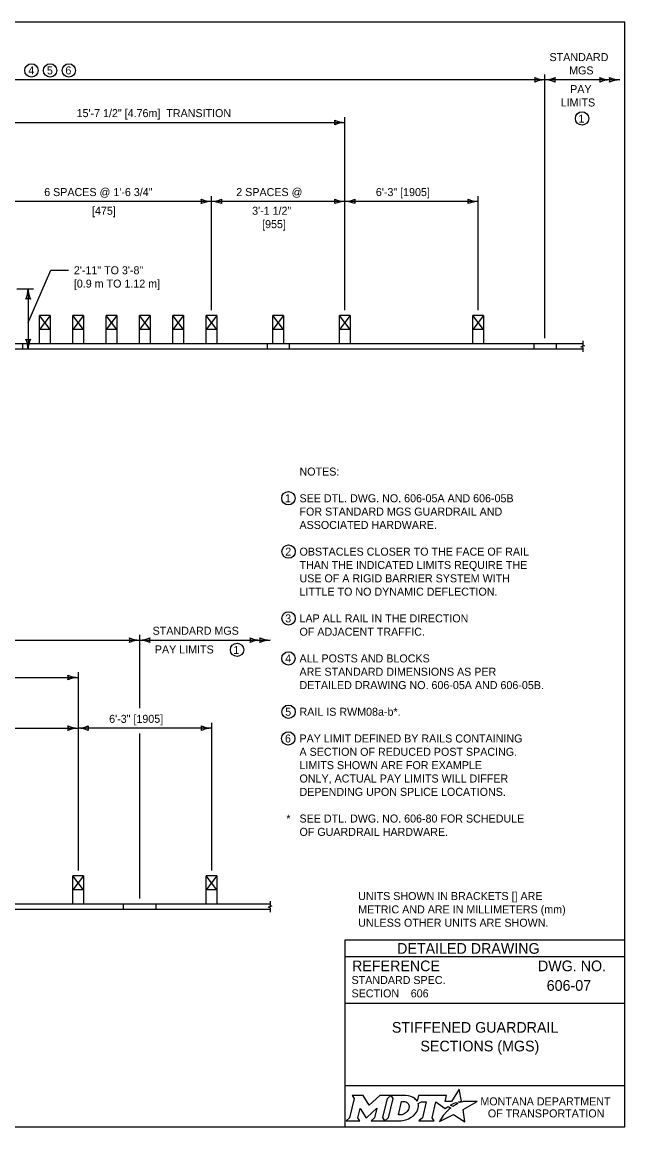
# Model space of a CAD drawing. Extents: x 49991.4 to 50044.5, y 49987.6 to 50011.4.
# Drawn here: x 50016.42 to 50020.94, y 49999.89 to 50008.16 of the extents above; entities that cross this region are included whole.
import ezdxf

# ---------------------------------------------------------------- set-up
doc = ezdxf.new("R2010")
doc.units = 0
for name, color, linetype in [('Default', 7, 'Continuous'), ('Level 1', 7, 'Continuous'), ('Level 2', 7, 'Continuous'), ('Level 3', 7, 'Continuous'), ('Level 4', 7, 'Continuous'), ('Level 6', 7, 'Continuous')]:
    doc.layers.add(name, color=color, linetype=linetype)

msp = doc.modelspace()

# ---------------------------------------------------------------- linework, layer by layer
at = {"layer": 'Default'}
for points in [[(50018.8933, 50000.1206), (50018.9074, 50000.0972), (50018.8739, 49999.9539), (50018.8482, 49999.9314), (50018.9498, 49999.9314), (50018.9363, 49999.9542), (50018.9525, 50000.0243), (50018.9962, 49999.9553), (50019.0015, 49999.9553), (50019.0766, 50000.0248), (50019.0602, 49999.9537), (50019.0355, 49999.9317), (50019.1371, 49999.9317), (50019.1233, 49999.955), (50019.1565, 50000.0974)], [(50019.1565, 50000.0974), (50019.1818, 50000.1206), (50019.0994, 50000.1206), (50019.0198, 50000.0476), (50018.9753, 50000.1203), (50018.8933, 50000.1206)], [(50019.2954, 50000.1206), (50019.1818, 50000.1206), (50019.1965, 50000.0977), (50019.1626, 49999.9539), (50019.1371, 49999.9317), (50019.2477, 49999.9317)], [(50019.7003, 50000.0679), (50019.69, 50000.0735), (50019.7016, 50000.0763), (50019.7132, 50000.0783), (50019.6958, 50000.1684), (50019.6363, 50000.0771), (50019.589, 50000.0764), (50019.5993, 50000.1205), (50019.3901, 50000.1206), (50019.38, 50000.0781), (50019.3742, 50000.0864)], [(50019.3194, 50000.0339), (50019.3182, 50000.0258), (50019.315, 50000.0165), (50019.3108, 50000.0083), (50019.3052, 50000.0008), (50019.2987, 49999.9939), (50019.2908, 49999.9876), (50019.2825, 49999.9829), (50019.2734, 49999.979), (50019.2643, 49999.9767), (50019.2551, 49999.9758), (50019.2392, 49999.9758), (50019.2628, 50000.0758), (50019.2788, 50000.0758), (50019.2864, 50000.0752), (50019.294, 50000.0733), (50019.3006, 50000.0703), (50019.3067, 50000.0661), (50019.3115, 50000.0611), (50019.3152, 50000.0551), (50019.3179, 50000.0489), (50019.3195, 50000.0415), (50019.3195, 50000.0385), (50019.3194, 50000.0339)], [(50019.3868, 50000.0615), (50019.4114, 50000.0746), (50019.4483, 50000.0746), (50019.4197, 49999.9541), (50019.3922, 49999.9314), (50019.5084, 49999.9314), (50019.4914, 49999.9543), (50019.5196, 50000.0745), (50019.5909, 50000.0228), (50019.612, 50000.0379), (50019.6317, 50000.027)], [(50019.5759, 49999.9711), (50019.5606, 49999.9467), (50019.5559, 49999.9392), (50019.5501, 49999.9306), (50019.5478, 49999.9263), (50019.6531, 49999.9794), (50019.737, 49999.9243), (50019.7239, 50000.017), (50019.8308, 50000.0754), (50019.7815, 50000.0762), (50019.7514, 50000.0766), (50019.7306, 50000.0769), (50019.7238, 50000.0754), (50019.7189, 50000.0742), (50019.7105, 50000.0719), (50019.7003, 50000.0679)], [(50019.6499, 50000.0403), (50019.6475, 50000.0386), (50019.6292, 50000.0482), (50019.6395, 50000.0539), (50019.6436, 50000.0561), (50019.6522, 50000.0601), (50019.6579, 50000.0627), (50019.6658, 50000.0657), (50019.6731, 50000.0684), (50019.6849, 50000.061), (50019.6809, 50000.0589), (50019.6763, 50000.0564), (50019.6721, 50000.0542), (50019.6671, 50000.0513), (50019.6652, 50000.0502), (50019.6625, 50000.0486), (50019.66, 50000.0472), (50019.6577, 50000.0456), (50019.6551, 50000.0438), (50019.6524, 50000.042), (50019.6499, 50000.0403)], [(50019.2934, 49999.939), (50019.3018, 49999.9416), (50019.3148, 49999.947), (50019.3352, 49999.958)], [(50019.5898, 49999.9872), (50019.5898, 49999.9872)]]:
    msp.add_lwpolyline(points, dxfattribs=at)
for centre, radius, start, end in [((50019.3185, 50000.0422), 0.0709, 339.53292, 15.85821), ((50019.2745, 50000.0595), 0.1183, 300.91025, 339.13831)]:
    msp.add_arc(centre, radius, start, end, dxfattribs=at)
for centre, major_axis, ratio, start_param, end_param in [((50019.2933, 50000.0732), (0.0834, -0.0037), 0.568097, 0.61298, 1.570796), ((50019.3489, 50000.0805), (0.0361, -0.0295), 0.469099, 1.225588, 1.570796), ((50019.6206, 50000.0173), (-0.0112, -0.0097), 0.021651, 3.157348, 6.283185), ((50019.5829, 49999.9791), (-0.00694, -0.00806), 0.008222, 0, 3.137361), ((50019.5996, 49999.9974), (-0.0098, -0.0102), 0.016458, 3.141593, 6.279097), ((50019.248, 50000.08), (0, 0.1484), 0.987302, 3.139398, 3.456847)]:
    msp.add_ellipse(centre, major_axis=major_axis, ratio=ratio, start_param=start_param, end_param=end_param, dxfattribs=at)
at = {"layer": 'Level 1'}
for p, q in [((50016.5483, 50005.7568), (50016.5483, 50005.9668)), ((50016.6271, 50005.8618), (50016.5483, 50005.9668)), ((50016.6271, 50005.9668), (50016.5483, 50005.8618)), ((50016.6271, 50005.9668), (50016.5483, 50005.9668)), ((50016.6271, 50005.9668), (50016.6271, 50005.7568)), ((50016.7983, 50005.7568), (50016.7983, 50005.9668)), ((50016.8771, 50005.8618), (50016.7983, 50005.9668)), ((50016.8771, 50005.9668), (50016.7983, 50005.8618)), ((50016.8771, 50005.9668), (50016.7983, 50005.9668)), ((50016.8771, 50005.9668), (50016.8771, 50005.7568)), ((50017.0483, 50005.7568), (50017.0483, 50005.9668)), ((50017.1271, 50005.8618), (50017.0483, 50005.9668)), ((50017.1271, 50005.9668), (50017.0483, 50005.8618)), ((50017.1271, 50005.9668), (50017.0483, 50005.9668)), ((50017.1271, 50005.9668), (50017.1271, 50005.7568)), ((50017.2983, 50005.7568), (50017.2983, 50005.9668)), ((50017.3771, 50005.8618), (50017.2983, 50005.9668)), ((50017.3771, 50005.9668), (50017.2983, 50005.8618)), ((50017.3771, 50005.9668), (50017.2983, 50005.9668)), ((50017.3771, 50005.9668), (50017.3771, 50005.7568)), ((50017.5483, 50005.7568), (50017.5483, 50005.9668)), ((50017.6271, 50005.8618), (50017.5483, 50005.9668)), ((50017.6271, 50005.9668), (50017.5483, 50005.8618)), ((50017.6271, 50005.9668), (50017.5483, 50005.9668)), ((50017.6271, 50005.9668), (50017.6271, 50005.7568)), ((50017.7983, 50005.7568), (50017.7983, 50005.9668)), ((50017.8771, 50005.8618), (50017.7983, 50005.9668)), ((50017.8771, 50005.9668), (50017.7983, 50005.8618)), ((50017.8771, 50005.9668), (50017.7983, 50005.9668)), ((50017.8771, 50005.9668), (50017.8771, 50005.7568)), ((50018.2983, 50005.7568), (50018.2983, 50005.9668)), ((50018.3771, 50005.8618), (50018.2983, 50005.9668)), ((50018.3771, 50005.9668), (50018.2983, 50005.8618)), ((50018.3771, 50005.9668), (50018.2983, 50005.9668)), ((50018.3771, 50005.9668), (50018.3771, 50005.7568)), ((50018.7983, 50005.7568), (50018.7983, 50005.9668)), ((50018.8771, 50005.8618), (50018.7983, 50005.9668)), ((50018.8771, 50005.9668), (50018.7983, 50005.8618)), ((50018.8771, 50005.9668), (50018.7983, 50005.9668)), ((50018.8771, 50005.9668), (50018.8771, 50005.7568)), ((50019.7983, 50005.7568), (50019.7983, 50005.9668)), ((50019.8771, 50005.8618), (50019.7983, 50005.9668)), ((50019.8771, 50005.9668), (50019.7983, 50005.8618)), ((50019.8771, 50005.9668), (50019.7983, 50005.9668)), ((50019.8771, 50005.9668), (50019.8771, 50005.7568)), ((50016.6271, 50005.8618), (50016.5483, 50005.8618)), ((50016.8771, 50005.8618), (50016.7983, 50005.8618)), ((50017.1271, 50005.8618), (50017.0483, 50005.8618)), ((50017.3771, 50005.8618), (50017.2983, 50005.8618)), ((50017.6271, 50005.8618), (50017.5483, 50005.8618)), ((50017.8771, 50005.8618), (50017.7983, 50005.8618)), ((50018.3771, 50005.8618), (50018.2983, 50005.8618)), ((50018.8771, 50005.8618), (50018.7983, 50005.8618)), ((50019.8771, 50005.8618), (50019.7983, 50005.8618)), ((50010.0544, 50005.7568), (50020.6214, 50005.7568)), ((50018.2544, 50005.7568), (50018.2544, 50005.7128)), ((50020.2544, 50005.7568), (50020.2544, 50005.7128)), ((50020.6214, 50005.7128), (50010.0544, 50005.7128)), ((50016.7985, 50001.5579), (50016.7985, 50001.7679)), ((50016.8773, 50001.6629), (50016.7985, 50001.7679)), ((50016.8773, 50001.7679), (50016.7985, 50001.6629)), ((50016.8773, 50001.7679), (50016.7985, 50001.7679)), ((50016.8773, 50001.7679), (50016.8773, 50001.5579)), ((50017.7985, 50001.5579), (50017.7985, 50001.7679)), ((50017.8773, 50001.6629), (50017.7985, 50001.7679)), ((50017.8773, 50001.7679), (50017.7985, 50001.6629)), ((50017.8773, 50001.7679), (50017.7985, 50001.7679)), ((50017.8773, 50001.7679), (50017.8773, 50001.5579)), ((50016.8773, 50001.6629), (50016.7985, 50001.6629)), ((50017.8773, 50001.6629), (50017.7985, 50001.6629)), ((50010.3981, 50001.5579), (50018.2773, 50001.5579)), ((50017.176, 50001.5579), (50017.176, 50001.5139)), ((50018.2773, 50001.5139), (50010.3981, 50001.5139))]:
    msp.add_line(p, q, dxfattribs=at)
msp.add_lwpolyline([(50020.9378, 50008.1646), (50009.7374, 50008.1646), (50009.7374, 49999.8856), (50020.9378, 49999.8856)], close=True, dxfattribs=at)
at = {"layer": 'Level 2'}
for centre in [(50016.488, 50007.8026), (50016.628, 50007.8026), (50016.768, 50007.8026), (50020.6161, 50007.4424), (50018.4143, 50004.5964), (50018.416, 50004.1964), (50018.4158, 50003.6964), (50018.0294, 50003.4606), (50018.4146, 50003.3964), (50018.4155, 50002.9964), (50018.4135, 50002.7964)]:
    msp.add_circle(centre, 0.05, dxfattribs=at)
at = {"layer": 'Level 3'}
for p, q in [((50020.8978, 50007.7324), (50009.7774, 50007.7324)), ((50020.3379, 50005.7968), (50020.3379, 50007.7724)), ((50016.3377, 50007.4124), (50018.8377, 50007.4124)), ((50018.8377, 50006.0068), (50018.8377, 50007.4524)), ((50017.8377, 50006.8208), (50016.3377, 50006.8208)), ((50017.8377, 50006.0068), (50017.8377, 50006.8608)), ((50018.8377, 50006.8208), (50017.8377, 50006.8208)), ((50019.8377, 50006.8208), (50018.8377, 50006.8208)), ((50019.8377, 50006.0068), (50019.8377, 50006.8608)), ((50016.3777, 50006.1646), (50016.5027, 50006.1646)), ((50016.4627, 50006.1646), (50016.4627, 50005.7128)), ((50010.3981, 50003.5335), (50018.2773, 50003.5335)), ((50017.2987, 50003.5735), (50017.2987, 50003.0235)), ((50016.8379, 50003.2935), (50016.8379, 50001.8079)), ((50011.8377, 50003.2535), (50016.8379, 50003.2535)), ((50014.8379, 50002.8735), (50016.8379, 50002.8735)), ((50017.8381, 50002.8735), (50016.8379, 50002.8735)), ((50017.8381, 50002.9135), (50017.8381, 50001.8079)), ((50017.2987, 50002.8335), (50017.2987, 50001.5979))]:
    msp.add_line(p, q, dxfattribs=at)
msp.add_lwpolyline([(50016.4627, 50005.913), (50016.633, 50006.3049), (50016.7659, 50006.3049)], dxfattribs=at)
for centre, radius, start, end in [((50020.3471, 50007.9545), 0.2223, 247.45601, 267.63952), ((50020.2097, 50007.7324), 0.0548, 342.13882, 17.86118), ((50020.3494, 50007.4997), 0.233, 92.82731, 112.07716), ((50020.3264, 50007.9651), 0.233, 272.82731, 292.07716), ((50020.3287, 50007.5103), 0.2223, 67.45601, 87.63952), ((50020.4661, 50007.7324), 0.0548, 162.13882, 197.86118), ((50020.8343, 50007.9545), 0.2223, 247.45601, 267.63952), ((50020.697, 50007.7324), 0.0548, 342.13882, 17.86118), ((50020.8367, 50007.4997), 0.233, 92.82731, 112.07716), ((50020.9078, 50007.9545), 0.2223, 247.45601, 267.63952), ((50020.7704, 50007.7324), 0.0548, 342.13882, 17.86118), ((50020.9101, 50007.4997), 0.233, 92.82731, 112.07716), ((50018.8469, 50007.6345), 0.2223, 247.45601, 267.63952), ((50018.7095, 50007.4124), 0.0548, 342.13882, 17.86118), ((50018.8492, 50007.1797), 0.233, 92.82731, 112.07716), ((50017.8469, 50007.043), 0.2223, 247.45601, 267.63952), ((50017.7095, 50006.8208), 0.0548, 342.13882, 17.86118), ((50017.8492, 50006.5881), 0.233, 92.82731, 112.07716), ((50017.8262, 50007.0535), 0.233, 272.82731, 292.07716), ((50017.8285, 50006.5987), 0.2223, 67.45601, 87.63952), ((50017.9659, 50006.8208), 0.0548, 162.13882, 197.86118), ((50018.8469, 50007.043), 0.2223, 247.45601, 267.63952), ((50018.7095, 50006.8208), 0.0548, 342.13882, 17.86118), ((50018.8492, 50006.5881), 0.233, 92.82731, 112.07716), ((50018.8262, 50007.0535), 0.233, 272.82731, 292.07716), ((50018.8285, 50006.5987), 0.2223, 67.45601, 87.63952), ((50018.9659, 50006.8208), 0.0548, 162.13882, 197.86118), ((50019.8469, 50007.043), 0.2223, 247.45601, 267.63952), ((50019.7095, 50006.8208), 0.0548, 342.13882, 17.86118), ((50019.8492, 50006.5881), 0.233, 92.82731, 112.07716), ((50016.2406, 50006.1738), 0.2223, 337.45601, 357.63952), ((50016.6954, 50006.1761), 0.233, 182.82731, 202.07716), ((50016.4627, 50006.0364), 0.0548, 72.13882, 107.86118), ((50016.4627, 50005.841), 0.0548, 252.13882, 287.86118), ((50016.23, 50005.7013), 0.233, 2.82731, 22.07716), ((50016.6848, 50005.7036), 0.2223, 157.45601, 177.63952), ((50017.3079, 50003.7556), 0.2223, 247.45601, 267.63952), ((50017.1705, 50003.5335), 0.0548, 342.13882, 17.86118), ((50017.3102, 50003.3007), 0.233, 92.82731, 112.07716), ((50017.2872, 50003.7662), 0.233, 272.82731, 292.07716), ((50017.2895, 50003.3113), 0.2223, 67.45601, 87.63952), ((50017.4269, 50003.5335), 0.0548, 162.13882, 197.86118), ((50018.213, 50003.7556), 0.2223, 247.45601, 267.63952), ((50018.0756, 50003.5335), 0.0548, 342.13882, 17.86118), ((50018.2153, 50003.3007), 0.233, 92.82731, 112.07716), ((50018.2864, 50003.7556), 0.2223, 247.45601, 267.63952), ((50018.1491, 50003.5335), 0.0548, 342.13882, 17.86118), ((50018.2888, 50003.3007), 0.233, 92.82731, 112.07716), ((50016.8471, 50003.4756), 0.2223, 247.45601, 267.63952), ((50016.7097, 50003.2535), 0.0548, 342.13882, 17.86118), ((50016.8494, 50003.0207), 0.233, 92.82731, 112.07716), ((50016.8471, 50003.0956), 0.2223, 247.45601, 267.63952), ((50016.7097, 50002.8735), 0.0548, 342.13882, 17.86118), ((50016.8494, 50002.6407), 0.233, 92.82731, 112.07716), ((50016.8287, 50003.0956), 0.2223, 272.36048, 292.54399), ((50016.8264, 50002.6407), 0.233, 67.92284, 87.17269), ((50016.9661, 50002.8735), 0.0548, 162.13882, 197.86118), ((50017.7099, 50002.8735), 0.0548, 342.13882, 17.86118), ((50017.8496, 50003.1062), 0.233, 247.92284, 267.17269), ((50017.8473, 50002.6513), 0.2223, 92.36048, 112.54399)]:
    msp.add_arc(centre, radius, start, end, dxfattribs=at)
at = {"layer": 'Level 4'}
for p, q in [((50016.4214, 50005.7568), (50016.4214, 50005.7128)), ((50018.4214, 50005.7568), (50018.4214, 50005.7128)), ((50020.4214, 50005.7568), (50020.4214, 50005.7128)), ((50017.4214, 50001.5579), (50017.4214, 50001.5139)), ((50020.9378, 50001.2856), (50018.8378, 50001.2856)), ((50018.8378, 50001.2856), (50018.8378, 49999.8856)), ((50020.9378, 50001.1606), (50018.8378, 50001.1606)), ((50020.5739, 50000.9455), (50020.5739, 50000.9455)), ((50019.3321, 50000.8861), (50019.3321, 50000.8861)), ((50020.9378, 50000.8106), (50018.8378, 50000.8106)), ((50019.8878, 50000.5615), (50019.8878, 50000.5615)), ((50020.9378, 50000.1925), (50018.8378, 50000.1925))]:
    msp.add_line(p, q, dxfattribs=at)
at = {"layer": 'Level 6'}
for p, q in [((50020.6351, 50005.7397), (50020.6077, 50005.7299)), ((50020.6214, 50005.7768), (50020.6214, 50005.7445)), ((50020.6351, 50005.7397), (50020.6214, 50005.7445)), ((50020.6214, 50005.7251), (50020.6077, 50005.7299)), ((50020.6214, 50005.7251), (50020.6214, 50005.6928)), ((50018.291, 50001.5407), (50018.2636, 50001.531)), ((50018.2773, 50001.5261), (50018.2636, 50001.531)), ((50018.2773, 50001.5779), (50018.2773, 50001.5456)), ((50018.291, 50001.5407), (50018.2773, 50001.5456)), ((50018.2773, 50001.5261), (50018.2773, 50001.4939))]:
    msp.add_line(p, q, dxfattribs=at)

# ---------------------------------------------------------------- texts
at = {"layer": 'Default'}
for s, p in [('MONTANA DEPARTMENT', (50019.854, 50000.0468)), ('OF TRANSPORTATION', (50019.9102, 49999.9568))]:
    msp.add_text(s, height=0.06, dxfattribs=at).set_placement(p)
at = {"layer": 'Level 2'}
for s, height, p in [('STANDARD ', 0.06, (50020.3726, 50007.8724)), ('4', 0.06, (50016.464, 50007.7726)), ('5', 0.06, (50016.604, 50007.7726)), ('6', 0.06, (50016.7424, 50007.7726)), ('MGS', 0.06, (50020.5195, 50007.7724)), ('PAY ', 0.06, (50020.5271, 50007.6324)), ('LIMITS', 0.06, (50020.4561, 50007.5324)), ('15\'-7 1/2" [4.76m]  TRANSITION', 0.06, (50016.8264, 50007.4524)), ('1', 0.06, (50020.5894, 50007.411)), ('6 SPACES @ 1\'-6 3/4"', 0.06, (50016.5836, 50006.8608)), (' 2 SPACES @ ', 0.06, (50018.0014, 50006.8608)), ('6\'-3" [1905]', 0.06, (50019.0703, 50006.8608)), (' [475]', 0.06, (50016.9195, 50006.7208)), ('3\'-1 1/2"', 0.06, (50018.1425, 50006.7208)), ('[955]', 0.06, (50018.2175, 50006.6208)), ('2\'-11" TO 3\'-8"', 0.06, (50016.8059, 50006.2749)), ('[0.9 m TO 1.12 m]', 0.06, (50016.8059, 50006.1749)), ('NOTES:', 0.06, (50018.4977, 50004.7664)), ('1', 0.06, (50018.3882, 50004.5665)), ('SEE DTL. DWG. NO. 606-05A AND 606-05B ', 0.06, (50018.4977, 50004.5664)), ('FOR STANDARD MGS GUARDRAIL AND ', 0.06, (50018.4977, 50004.4664)), ('ASSOCIATED HARDWARE.', 0.06, (50018.4977, 50004.3664)), ('2', 0.06, (50018.3908, 50004.1664)), ('OBSTACLES CLOSER TO THE FACE OF RAIL', 0.06, (50018.4977, 50004.1664)), ('THAN THE INDICATED LIMITS REQUIRE THE', 0.06, (50018.4977, 50004.0664)), ('USE OF A RIGID BARRIER SYSTEM WITH', 0.06, (50018.4977, 50003.9664)), ('LITTLE TO NO DYNAMIC DEFLECTION.', 0.06, (50018.4977, 50003.8664)), ('3', 0.06, (50018.3906, 50003.6664)), ('LAP ALL RAIL IN THE DIRECTION', 0.06, (50018.4977, 50003.6664)), ('STANDARD MGS', 0.06, (50017.3962, 50003.5735)), ('OF ADJACENT TRAFFIC.', 0.06, (50018.4977, 50003.5664)), ('PAY LIMITS', 0.06, (50017.4131, 50003.4335)), ('1', 0.06, (50018.0014, 50003.4292)), ('4', 0.06, (50018.3906, 50003.3664)), ('ALL POSTS AND BLOCKS', 0.06, (50018.4977, 50003.3664)), ('ARE STANDARD DIMENSIONS AS PER ', 0.06, (50018.4977, 50003.2664)), ('DETAILED DRAWING NO. 606-05A AND 606-05B.', 0.06, (50018.4977, 50003.1664)), ('5', 0.06, (50018.3906, 50002.9664)), ('RAIL IS RWM08a-b*. ', 0.06, (50018.4977, 50002.9664)), ('6\'-3" [1905]', 0.06, (50017.0705, 50002.9135)), ('6', 0.06, (50018.389, 50002.7664)), ('PAY LIMIT DEFINED BY RAILS CONTAINING', 0.06, (50018.4977, 50002.7664)), ('A SECTION OF REDUCED POST SPACING. ', 0.06, (50018.4977, 50002.6664)), ('LIMITS SHOWN ARE FOR EXAMPLE', 0.06, (50018.4977, 50002.5664)), ('ONLY, ACTUAL PAY LIMITS WILL DIFFER ', 0.06, (50018.4977, 50002.4664)), ('DEPENDING UPON SPLICE LOCATIONS. ', 0.06, (50018.4977, 50002.3664)), ('*', 0.06, (50018.3992, 50002.1664)), ('SEE DTL. DWG. NO. 606-80 FOR SCHEDULE ', 0.06, (50018.4977, 50002.1664)), ('OF GUARDRAIL HARDWARE.', 0.06, (50018.4977, 50002.0664)), ('UNITS SHOWN IN BRACKETS [] ARE ', 0.06, (50018.9378, 50001.5856)), ('METRIC AND ARE IN MILLIMETERS (mm) ', 0.06, (50018.9378, 50001.4856)), ('UNLESS OTHER UNITS ARE SHOWN.', 0.06, (50018.9378, 50001.3856)), ('606-07', 0.08, (50020.3513, 50000.9055)), ('606', 0.06, (50019.3321, 50000.8561)), ('STIFFENED GUARDRAIL', 0.08, (50019.1906, 50000.5915)), ('SECTIONS (MGS)', 0.08, (50019.4043, 50000.4515))]:
    msp.add_text(s, height=height, dxfattribs=at).set_placement(p)
at = {"layer": 'Level 4'}
for s, height, p in [('DETAILED DRAWING', 0.0799, (50019.2295, 50001.1831)), ('REFERENCE', 0.08, (50018.8914, 50001.0522)), ('DWG. NO.', 0.08, (50020.2856, 50001.0522)), ('STANDARD SPEC.', 0.06, (50018.8881, 50000.9562)), ('SECTION', 0.06, (50018.8881, 50000.8562))]:
    msp.add_text(s, height=height, dxfattribs=at).set_placement(p)

doc.saveas('drawing.dxf')
